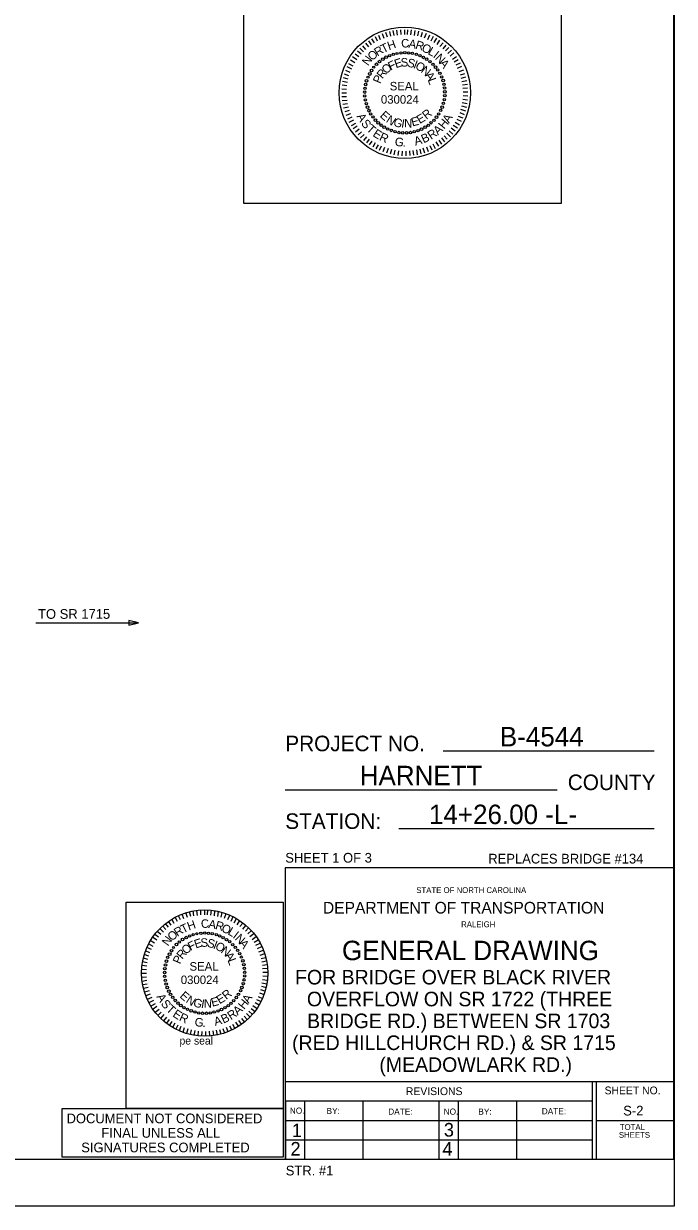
# Model space of a CAD drawing. Extents: x -20 to 509, y -659 to 21.
# Drawn here: x 197.5 to 264.5, y -176.3 to -54.6 of the extents above; entities that cross this region are included whole.
import ezdxf

# ---------------------------------------------------------------- set-up
doc = ezdxf.new("R2010")
doc.units = 0
for name, color, linetype in [('Arrowhead Terminators CELL', 7, 'Continuous'), ('Dimension Lines', 7, 'Continuous'), ('Peseal', 7, 'Continuous'), ('Plan Sheet CELL', 7, 'Continuous'), ('Plot Shape CELL', 7, 'Continuous'), ('Sheet Sticker Exception Certification CELL', 7, 'Continuous'), ('Subtitle Text', 7, 'Continuous'), ('Text', 7, 'Continuous'), ('Title Text', 7, 'Continuous'), ('User Information Notes', 7, 'Continuous'), ('User Information Notes CELL', 7, 'Continuous')]:
    doc.layers.add(name, color=color, linetype=linetype)

msp = doc.modelspace()

# ---------------------------------------------------------------- linework, layer by layer
at = {"layer": 'Arrowhead Terminators CELL'}
msp.add_lwpolyline([(209.32, -116.24), (208.32, -115.99), (208.32, -116.49)], close=True, dxfattribs=at)
at = {"layer": 'Dimension Lines'}
msp.add_line((198.75, -116.24), (209.32, -116.24), dxfattribs=at)
at = {"layer": 'Peseal'}
for p, q in [((233.94, -56.35), (233.72, -55.92)), ((234.25, -56.2), (234.06, -55.76)), ((234.62, -56.07), (234.44, -55.6)), ((234.97, -55.95), (234.81, -55.45)), ((235.31, -55.85), (235.19, -55.35)), ((235.66, -55.76), (235.56, -55.26)), ((236, -55.73), (235.94, -55.23)), ((236.37, -55.67), (236.34, -55.17)), ((236.75, -55.67), (236.75, -55.17)), ((237.03, -55.67), (237.06, -55.17)), ((237.37, -55.7), (237.44, -55.2)), ((237.75, -55.76), (237.81, -55.26)), ((238.09, -55.82), (238.19, -55.32)), ((238.44, -55.92), (238.56, -55.42)), ((238.78, -56.01), (238.97, -55.54)), ((239.12, -56.17), (239.34, -55.7)), ((239.47, -56.32), (239.69, -55.85)), ((232.5, -57.45), (232.12, -57.07)), ((232.75, -57.2), (232.44, -56.82)), ((233.03, -56.95), (232.72, -56.57)), ((233.31, -56.73), (233.03, -56.32)), ((233.62, -56.54), (233.37, -56.1)), ((239.78, -56.48), (240.03, -56.04)), ((240.09, -56.7), (240.37, -56.26)), ((240.37, -56.89), (240.69, -56.51)), ((240.69, -57.14), (241, -56.76)), ((240.94, -57.35), (241.28, -57.01)), ((231.59, -58.57), (231.16, -58.32)), ((231.81, -58.26), (231.37, -57.98)), ((232, -57.98), (231.62, -57.7)), ((232.25, -57.7), (231.87, -57.39)), ((241.19, -57.64), (241.56, -57.29)), ((241.41, -57.89), (241.81, -57.57)), ((241.66, -58.2), (242.06, -57.92)), ((241.84, -58.48), (242.25, -58.23)), ((231.12, -59.57), (230.66, -59.39)), ((231.28, -59.23), (230.81, -59.01)), ((231.44, -58.92), (230.97, -58.67)), ((242.03, -58.79), (242.47, -58.57)), ((242.19, -59.14), (242.62, -58.92)), ((242.34, -59.48), (242.81, -59.29)), ((230.84, -60.6), (230.34, -60.51)), ((230.91, -60.26), (230.44, -60.14)), ((231, -59.92), (230.53, -59.76)), ((242.47, -59.82), (242.94, -59.67)), ((242.56, -60.17), (243.03, -60.04)), ((242.62, -60.51), (243.12, -60.42)), ((242.69, -60.85), (243.19, -60.79)), ((230.75, -61.32), (230.25, -61.29)), ((230.75, -61.7), (230.25, -61.7)), ((230.75, -62.07), (230.25, -62.1)), ((230.78, -60.95), (230.31, -60.89)), ((242.72, -61.2), (243.22, -61.17)), ((242.75, -61.57), (243.25, -61.57)), ((242.75, -61.95), (243.25, -61.98)), ((230.81, -62.45), (230.31, -62.51)), ((230.84, -62.79), (230.37, -62.89)), ((230.94, -63.14), (230.44, -63.26)), ((242.59, -63.01), (243.09, -63.14)), ((242.66, -62.67), (243.16, -62.76)), ((242.72, -62.32), (243.22, -62.39)), ((231.03, -63.48), (230.56, -63.64)), ((231.16, -63.82), (230.69, -64.01)), ((231.31, -64.17), (230.84, -64.39)), ((231.47, -64.48), (231, -64.73)), ((242.09, -64.39), (242.56, -64.6)), ((242.25, -64.07), (242.72, -64.26)), ((242.41, -63.7), (242.87, -63.89)), ((242.5, -63.35), (243, -63.51)), ((231.66, -64.82), (231.22, -65.07)), ((231.84, -65.1), (231.44, -65.39)), ((232.06, -65.42), (231.66, -65.73)), ((232.28, -65.7), (231.94, -66.01)), ((241.31, -65.57), (241.69, -65.92)), ((241.53, -65.29), (241.94, -65.6)), ((241.72, -65.01), (242.16, -65.29)), ((241.94, -64.7), (242.37, -64.95)), ((232.56, -65.95), (232.19, -66.32)), ((232.81, -66.2), (232.5, -66.57)), ((233.09, -66.45), (232.81, -66.82)), ((233.37, -66.64), (233.09, -67.04)), ((233.69, -66.82), (233.44, -67.26)), ((239.62, -66.92), (239.87, -67.39)), ((239.94, -66.73), (240.22, -67.17)), ((240.25, -66.54), (240.53, -66.95)), ((240.53, -66.32), (240.84, -66.73)), ((240.81, -66.1), (241.12, -66.45)), ((241.06, -65.82), (241.44, -66.2)), ((234, -67.01), (233.78, -67.45)), ((234.31, -67.17), (234.12, -67.6)), ((234.66, -67.29), (234.5, -67.76)), ((235.03, -67.42), (234.87, -67.89)), ((235.37, -67.51), (235.25, -67.98)), ((235.72, -67.57), (235.62, -68.07)), ((236.09, -67.64), (236.03, -68.14)), ((236.47, -67.67), (236.44, -68.17)), ((236.84, -67.67), (236.84, -68.17)), ((237.22, -67.64), (237.25, -68.14)), ((237.59, -67.6), (237.66, -68.1)), ((237.94, -67.54), (238.03, -68.04)), ((238.28, -67.48), (238.41, -67.95)), ((238.62, -67.35), (238.78, -67.85)), ((238.97, -67.23), (239.16, -67.7)), ((239.31, -67.1), (239.53, -67.54)), ((214.36, -146.57), (214.2, -146.07)), ((214.7, -146.48), (214.58, -145.98)), ((215.04, -146.39), (214.95, -145.89)), ((215.39, -146.35), (215.33, -145.85)), ((215.76, -146.29), (215.73, -145.79)), ((216.14, -146.29), (216.14, -145.79)), ((216.42, -146.29), (216.45, -145.79)), ((216.76, -146.32), (216.83, -145.82)), ((217.14, -146.39), (217.2, -145.89)), ((217.48, -146.45), (217.58, -145.95)), ((217.83, -146.54), (217.95, -146.04)), ((212.42, -147.57), (212.11, -147.2)), ((212.7, -147.35), (212.42, -146.95)), ((213.01, -147.17), (212.76, -146.73)), ((213.33, -146.98), (213.11, -146.54)), ((213.64, -146.82), (213.45, -146.39)), ((214.01, -146.7), (213.83, -146.23)), ((218.17, -146.64), (218.36, -146.17)), ((218.51, -146.79), (218.73, -146.32)), ((218.86, -146.95), (219.08, -146.48)), ((219.17, -147.1), (219.42, -146.67)), ((219.48, -147.32), (219.76, -146.89)), ((219.76, -147.51), (220.08, -147.14)), ((211.39, -148.6), (211.01, -148.32)), ((211.64, -148.32), (211.26, -148.01)), ((211.89, -148.07), (211.51, -147.7)), ((212.14, -147.82), (211.83, -147.45)), ((220.08, -147.76), (220.39, -147.39)), ((220.33, -147.98), (220.67, -147.64)), ((220.58, -148.26), (220.95, -147.92)), ((220.79, -148.51), (221.2, -148.2)), ((210.67, -149.85), (210.2, -149.64)), ((210.83, -149.54), (210.36, -149.29)), ((210.98, -149.2), (210.54, -148.95)), ((211.2, -148.89), (210.76, -148.6)), ((221.04, -148.82), (221.45, -148.54)), ((221.23, -149.1), (221.64, -148.85)), ((221.42, -149.42), (221.86, -149.2)), ((221.58, -149.76), (222.01, -149.54)), ((210.29, -150.89), (209.83, -150.76)), ((210.39, -150.54), (209.92, -150.39)), ((210.51, -150.2), (210.04, -150.01)), ((221.73, -150.1), (222.2, -149.92)), ((221.86, -150.45), (222.33, -150.29)), ((221.95, -150.79), (222.42, -150.67)), ((210.14, -151.95), (209.64, -151.92)), ((210.17, -151.57), (209.7, -151.51)), ((210.23, -151.23), (209.73, -151.14)), ((222.01, -151.14), (222.51, -151.04)), ((222.08, -151.48), (222.58, -151.42)), ((222.11, -151.82), (222.61, -151.79)), ((210.14, -152.32), (209.64, -152.32)), ((210.14, -152.7), (209.64, -152.73)), ((210.2, -153.07), (209.7, -153.14)), ((222.04, -153.29), (222.54, -153.39)), ((222.11, -152.95), (222.61, -153.01)), ((222.14, -152.2), (222.64, -152.2)), ((222.14, -152.57), (222.64, -152.6)), ((210.23, -153.42), (209.76, -153.51)), ((210.33, -153.76), (209.83, -153.89)), ((210.42, -154.1), (209.95, -154.26)), ((210.54, -154.45), (210.08, -154.64)), ((221.79, -154.32), (222.26, -154.51)), ((221.89, -153.98), (222.39, -154.14)), ((221.98, -153.64), (222.48, -153.76)), ((210.7, -154.79), (210.23, -155.01)), ((210.86, -155.1), (210.39, -155.35)), ((211.04, -155.45), (210.61, -155.7)), ((211.23, -155.73), (210.83, -156.01)), ((221.11, -155.64), (221.54, -155.92)), ((221.33, -155.32), (221.76, -155.57)), ((221.48, -155.01), (221.95, -155.23)), ((221.64, -154.7), (222.11, -154.89)), ((211.45, -156.04), (211.04, -156.35)), ((211.67, -156.32), (211.33, -156.64)), ((211.95, -156.57), (211.58, -156.95)), ((212.2, -156.82), (211.89, -157.2)), ((219.92, -156.95), (220.23, -157.35)), ((220.2, -156.73), (220.51, -157.07)), ((220.45, -156.45), (220.83, -156.82)), ((220.7, -156.2), (221.08, -156.54)), ((220.92, -155.92), (221.33, -156.23)), ((212.48, -157.07), (212.2, -157.45)), ((212.76, -157.26), (212.48, -157.67)), ((213.08, -157.45), (212.83, -157.89)), ((213.39, -157.64), (213.17, -158.07)), ((213.7, -157.79), (213.51, -158.23)), ((214.04, -157.92), (213.89, -158.39)), ((214.42, -158.04), (214.26, -158.51)), ((214.76, -158.14), (214.64, -158.6)), ((215.11, -158.2), (215.01, -158.7)), ((215.48, -158.26), (215.42, -158.76)), ((216.61, -158.26), (216.64, -158.76)), ((216.98, -158.23), (217.04, -158.73)), ((217.33, -158.17), (217.42, -158.67)), ((217.67, -158.1), (217.79, -158.57)), ((218.01, -157.98), (218.17, -158.48)), ((218.36, -157.85), (218.54, -158.32)), ((218.7, -157.73), (218.92, -158.17)), ((219.01, -157.54), (219.26, -158.01)), ((219.33, -157.35), (219.61, -157.79)), ((219.64, -157.17), (219.92, -157.57)), ((215.86, -158.29), (215.83, -158.79)), ((216.23, -158.29), (216.23, -158.79))]:
    msp.add_line(p, q, dxfattribs=at)
for centre, radius in [((234.14, -58.46), 0.134), ((234.48, -58.21), 0.134), ((234.84, -58.01), 0.14), ((235.2, -57.84), 0.119), ((235.56, -57.71), 0.114), ((235.95, -57.62), 0.11), ((236.36, -57.57), 0.126), ((236.75, -57.54), 0.125), ((237.14, -57.57), 0.126), ((237.53, -57.6), 0.129), ((237.94, -57.71), 0.114), ((238.3, -57.84), 0.119), ((238.66, -58.03), 0.126), ((239, -58.21), 0.126), ((239.33, -58.45), 0.122), ((233.14, -59.73), 0.144), ((233.33, -59.37), 0.134), ((233.55, -59.03), 0.11), ((233.84, -58.73), 0.133), ((239.64, -58.73), 0.122), ((239.91, -59.03), 0.122), ((240.14, -59.32), 0.126), ((240.36, -59.67), 0.126), ((232.72, -60.82), 0.129), ((232.81, -60.43), 0.134), ((232.95, -60.06), 0.119), ((240.55, -60.03), 0.119), ((240.69, -60.4), 0.134), ((240.78, -60.79), 0.129), ((232.62, -61.6), 0.125), ((232.62, -61.99), 0.126), ((232.66, -61.21), 0.126), ((240.84, -61.18), 0.126), ((240.87, -61.57), 0.125), ((240.87, -61.96), 0.126), ((232.69, -62.4), 0.126), ((232.78, -62.79), 0.129), ((232.91, -63.15), 0.134), ((240.59, -63.15), 0.134), ((240.72, -62.76), 0.129), ((240.81, -62.37), 0.126), ((233.06, -63.51), 0.14), ((233.23, -63.85), 0.126), ((233.47, -64.15), 0.122), ((233.72, -64.48), 0.133), ((239.75, -64.49), 0.122), ((240.02, -64.18), 0.134), ((240.23, -63.85), 0.126), ((240.45, -63.48), 0.126), ((234, -64.76), 0.133), ((234.3, -64.99), 0.134), ((234.62, -65.21), 0.126), ((234.98, -65.4), 0.119), ((235.36, -65.54), 0.134), ((235.75, -65.67), 0.129), ((236.14, -65.76), 0.126), ((236.53, -65.79), 0.125), ((236.94, -65.79), 0.125), ((237.33, -65.76), 0.126), ((237.72, -65.67), 0.129), ((238.11, -65.56), 0.119), ((238.47, -65.42), 0.14), ((238.84, -65.21), 0.126), ((239.17, -65.01), 0.122), ((239.45, -64.76), 0.122), ((214.23, -148.64), 0.14), ((214.59, -148.46), 0.119), ((214.95, -148.34), 0.114), ((215.34, -148.24), 0.11), ((215.75, -148.2), 0.126), ((216.14, -148.17), 0.125), ((216.53, -148.2), 0.126), ((216.92, -148.23), 0.129), ((217.33, -148.34), 0.114), ((217.68, -148.46), 0.119), ((218.04, -148.65), 0.126), ((212.93, -149.65), 0.11), ((213.23, -149.35), 0.133), ((213.53, -149.09), 0.134), ((213.87, -148.84), 0.134), ((218.39, -148.84), 0.126), ((218.72, -149.07), 0.122), ((219.03, -149.35), 0.122), ((219.29, -149.65), 0.122), ((212.2, -151.06), 0.134), ((212.34, -150.68), 0.119), ((212.53, -150.35), 0.144), ((212.72, -149.99), 0.134), ((219.53, -149.95), 0.126), ((219.75, -150.29), 0.126), ((219.93, -150.65), 0.119), ((220.08, -151.03), 0.134), ((212.01, -152.23), 0.125), ((212.04, -151.84), 0.126), ((212.11, -151.45), 0.129), ((220.17, -151.42), 0.129), ((220.23, -151.81), 0.126), ((220.26, -152.2), 0.125), ((212.01, -152.62), 0.126), ((212.08, -153.03), 0.126), ((212.17, -153.42), 0.129), ((220.11, -153.39), 0.129), ((220.2, -152.99), 0.126), ((220.26, -152.59), 0.126), ((212.29, -153.78), 0.134), ((212.45, -154.14), 0.14), ((212.62, -154.48), 0.126), ((219.62, -154.48), 0.126), ((219.84, -154.1), 0.126), ((219.98, -153.78), 0.134), ((212.86, -154.78), 0.122), ((213.11, -155.1), 0.133), ((213.39, -155.39), 0.133), ((213.68, -155.62), 0.134), ((214.01, -155.84), 0.126), ((218.23, -155.84), 0.126), ((218.56, -155.64), 0.122), ((218.84, -155.39), 0.122), ((219.14, -155.12), 0.122), ((219.4, -154.81), 0.134), ((214.37, -156.03), 0.119), ((214.75, -156.17), 0.134), ((215.14, -156.29), 0.129), ((215.53, -156.39), 0.126), ((215.92, -156.42), 0.125), ((216.33, -156.42), 0.125), ((216.72, -156.39), 0.126), ((217.11, -156.29), 0.129), ((217.5, -156.18), 0.119), ((217.86, -156.04), 0.14)]:
    msp.add_circle(centre, radius, dxfattribs=at)
at = {"layer": 'Plan Sheet CELL'}
for p, q in [((264.43, -3.45), (264.43, -171.45)), ((262.44, -129.45), (240.7, -129.45)), ((252.44, -133.45), (224.44, -133.45)), ((262.44, -137.45), (236.12, -137.45)), ((264.43, -141.45), (224.44, -141.45)), ((224.44, -141.45), (224.44, -171.45)), ((224.44, -163.45), (264.43, -163.45)), ((256.04, -163.45), (256.04, -171.45)), ((256.44, -163.45), (256.44, -171.45)), ((224.44, -165.45), (256.05, -165.45)), ((224.46, -165.45), (224.46, -171.45)), ((226.43, -165.45), (226.43, -171.45)), ((232.43, -165.48), (232.43, -171.48)), ((240.24, -165.45), (240.24, -171.5)), ((242.24, -165.45), (242.24, -171.46)), ((248.24, -165.45), (248.24, -171.46)), ((224.44, -167.45), (256.12, -167.45)), ((256.44, -167.45), (264.36, -167.45)), ((224.44, -169.45), (256.05, -169.45)), ((8.43, -171.45), (264.43, -171.45)), ((264.5, -176.3), (264.5, -176.3))]:
    msp.add_line(p, q, dxfattribs=at)
msp.add_lwpolyline([(220.15, -73.02), (252.88, -73.02), (252.88, -51.02), (220.15, -51.02)], close=True, dxfattribs=at)
at = {"layer": 'Plot Shape CELL'}
msp.add_lwpolyline([(0, -0.3), (264.5, -0.3), (264.5, -176.3), (0, -176.3)], close=True, dxfattribs=at)
at = {"layer": 'Sheet Sticker Exception Certification CELL'}
msp.add_lwpolyline([(201.45, -166.24), (224.24, -166.24), (224.24, -171.25), (201.45, -171.25)], close=True, dxfattribs=at)
at = {"layer": 'User Information Notes'}
for p, q in [((236.75, -61.67), (236.75, -61.67)), ((252.88, -73.02), (252.88, -73.02)), ((216.14, -152.29), (216.14, -152.29))]:
    msp.add_line(p, q, dxfattribs=at)
msp.add_circle((236.75, -61.67), 6.77, dxfattribs=at)
at = {"layer": 'User Information Notes CELL'}
msp.add_line((216.14, -152.29), (216.14, -152.29), dxfattribs=at)
msp.add_lwpolyline([(208.04, -144.99), (224.24, -144.99), (224.24, -166.24), (208.04, -166.24)], close=True, dxfattribs=at)
msp.add_circle((216.14, -152.29), 6.5, dxfattribs=at)

# ---------------------------------------------------------------- texts
at = {"layer": 'Dimension Lines'}
msp.add_text('STR. #1', height=1, dxfattribs=at).set_placement((224.49, -173.12))
at = {"layer": 'Peseal'}
for s, height, rotation, p in [('R', 0.875, 32.9699, (233.94, -57.95)), ('T', 0.875, 25.943, (234.53, -57.6)), ('H', 0.875, 18.9162, (235.12, -57.29)), ('C', 0.875, 4.8625, (236.41, -57.04)), ('A', 0.875, 350.8088, (237.09, -57.01)), ('R', 0.875, 343.7819, (237.78, -57.1)), ('O', 0.875, 336.7551, (238.41, -57.35)), ('L', 0.875, 329.7282, (239.06, -57.64)), ('N', 0.875, 54.0504, (232.97, -58.95)), ('O', 0.875, 39.9967, (233.37, -58.42)), ('F', 0.875, 26.4777, (235.28, -59.39)), ('E', 0.875, 18.4448, (235.84, -59.14)), ('S', 0.875, 2.3789, (236.34, -58.98)), ('S', 0.875, 346.313, (236.94, -58.95)), ('I', 0.875, 338.28, (237.56, -59.1)), ('I', 0.875, 322.7014, (239.59, -57.98)), ('N', 0.875, 315.6745, (239.81, -58.17)), ('A', 0.875, 308.6477, (240.25, -58.64)), ('R', 0.875, 50.5765, (234.44, -60.29)), ('O', 0.875, 42.5436, (234.84, -59.79)), ('O', 0.875, 330.2471, (237.75, -59.14)), ('N', 0.875, 322.2141, (238.34, -59.51)), ('A', 0.875, 306.1483, (238.78, -59.89)), ('P', 0.875, 66.6424, (234.22, -60.79)), ('L', 0.875, 290.0824, (239.09, -60.32)), ('A', 0.887, 300.3993, (231.75, -64.09)), ('S', 0.887, 309.4349, (232.19, -64.85)), ('E', 0.875, 318.5179, (234.12, -64.1)), ('N', 0.875, 326.5361, (234.75, -64.64)), ('G', 0.875, 342.5725, (235.5, -65.04)), ('I', 0.875, 350.5906, (236.34, -65.23)), ('N', 0.875, 358.6088, (236.66, -65.23)), ('E', 0.875, 14.6452, (237.53, -65.14)), ('E', 0.875, 30.6815, (238.28, -64.89)), ('R', 0.875, 38.6997, (238.97, -64.45)), ('H', 0.887, 51.3597, (240.8, -65.47)), ('A', 0.887, 59.6007, (241.31, -64.85)), ('T', 0.887, 318.1096, (232.73, -65.5)), ('E', 0.887, 327.1453, (233.38, -66.08)), ('R', 0.887, 33.5776, (239.45, -66.52)), ('A', 0.887, 42.3241, (240.16, -66.06)), ('R', 0.888, 335.458, (234.05, -66.52)), ('G', 0.887, 353.3858, (235.68, -67.12)), ('A', 0.887, 15.7955, (237.84, -67.11)), ('B', 0.887, 24.8312, (238.68, -66.88)), ('.', 0.887, 2.1323, (236.52, -67.22)), ('T', 0.875, 25.943, (213.92, -148.23)), ('H', 0.875, 18.9162, (214.51, -147.92)), ('C', 0.875, 4.8625, (215.79, -147.67)), ('A', 0.875, 350.8088, (216.48, -147.64)), ('R', 0.875, 343.7819, (217.17, -147.73)), ('O', 0.875, 336.7551, (217.79, -147.98)), ('N', 0.875, 54.0504, (212.36, -149.57)), ('O', 0.875, 39.9967, (212.76, -149.04)), ('R', 0.875, 32.9699, (213.33, -148.57)), ('L', 0.875, 329.7282, (218.45, -148.26)), ('I', 0.875, 322.7014, (218.98, -148.6)), ('N', 0.875, 315.6745, (219.2, -148.79)), ('O', 0.875, 42.5436, (214.23, -150.42)), ('F', 0.875, 26.4777, (214.67, -150.01)), ('E', 0.875, 18.4448, (215.23, -149.76)), ('S', 0.875, 2.3789, (215.73, -149.6)), ('S', 0.875, 346.313, (216.33, -149.57)), ('I', 0.875, 338.28, (216.95, -149.73)), ('O', 0.875, 330.2471, (217.14, -149.76)), ('N', 0.875, 322.2141, (217.73, -150.14)), ('A', 0.875, 308.6477, (219.64, -149.26)), ('P', 0.875, 66.6424, (213.61, -151.42)), ('R', 0.875, 50.5765, (213.83, -150.92)), ('A', 0.875, 306.1483, (218.17, -150.51)), ('L', 0.875, 290.0824, (218.48, -150.95)), ('A', 0.887, 300.3993, (211.14, -154.72)), ('E', 0.875, 318.5179, (213.51, -154.73)), ('N', 0.875, 326.5361, (214.14, -155.26)), ('E', 0.875, 30.6815, (217.67, -155.51)), ('R', 0.875, 38.6997, (218.36, -155.07)), ('A', 0.887, 59.6007, (220.69, -155.47)), ('S', 0.887, 309.4349, (211.58, -155.47)), ('T', 0.887, 318.1096, (212.11, -156.12)), ('G', 0.875, 342.5725, (214.89, -155.67)), ('I', 0.875, 350.5906, (215.73, -155.85)), ('N', 0.875, 358.6088, (216.04, -155.85)), ('E', 0.875, 14.6452, (216.92, -155.76)), ('A', 0.887, 42.3241, (219.54, -156.68)), ('H', 0.887, 51.3597, (220.19, -156.09)), ('E', 0.887, 327.1453, (212.77, -156.71)), ('R', 0.888, 335.458, (213.44, -157.15)), ('G', 0.887, 353.3858, (215.07, -157.74)), ('A', 0.887, 15.7955, (217.23, -157.74)), ('B', 0.887, 24.8312, (218.07, -157.5)), ('R', 0.887, 33.5776, (218.84, -157.15)), ('.', 0.887, 2.1323, (215.91, -157.84))]:
    msp.add_text(s, height=height, rotation=rotation, dxfattribs=at).set_placement(p)
for s, p in [('SEAL', (235.19, -61.42)), ('030024', (234.29, -62.79)), ('SEAL', (214.58, -152.04)), ('030024', (213.68, -153.42))]:
    msp.add_text(s, height=0.875, dxfattribs=at).set_placement(p)
at = {"layer": 'Plan Sheet CELL'}
for s, height, p in [('PROJECT NO.', 1.6, (224.44, -129.45)), ('COUNTY', 1.6, (253.53, -133.45)), ('STATION:', 1.6, (224.44, -137.45)), ('SHEET 1 OF 3', 1, (224.44, -140.92)), ('STATE OF NORTH CAROLINA', 0.6, (237.93, -144.05)), ('DEPARTMENT OF TRANSPORTATION', 1.2, (228.32, -146.16)), ('RALEIGH', 0.6, (242.55, -147.57)), ('REVISIONS', 0.8, (236.86, -164.85)), ('SHEET NO.', 0.8, (257.32, -164.77)), ('NO.', 0.637, (224.91, -166.77)), ('BY:', 0.637, (228.69, -166.8)), ('DATE:', 0.637, (235.04, -166.87)), ('NO.', 0.637, (240.75, -166.87)), ('BY:', 0.637, (244.32, -166.87)), ('DATE:', 0.637, (250.85, -166.83)), ('1', 1.4, (225.12, -169.18)), ('3', 1.4, (240.77, -169.12)), ('TOTAL', 0.6, (258.89, -168.44)), ('SHEETS', 0.6, (258.79, -169.25)), ('2', 1.4, (224.98, -171.08)), ('4', 1.4, (240.62, -171.08))]:
    msp.add_text(s, height=height, dxfattribs=at).set_placement(p)
at = {"layer": 'Sheet Sticker Exception Certification CELL'}
for s, p in [('DOCUMENT NOT CONSIDERED', (201.92, -167.75)), ('FINAL UNLESS ALL', (205.5, -169.24)), ('SIGNATURES COMPLETED', (203.43, -170.74))]:
    msp.add_text(s, height=0.9978, dxfattribs=at).set_placement(p)
at = {"layer": 'Subtitle Text'}
for s, p in [('FOR BRIDGE OVER BLACK RIVER', (225.45, -153.46)), ('OVERFLOW ON SR 1722 (THREE', (226.67, -155.71)), ('BRIDGE RD.) BETWEEN SR 1703', (226.69, -157.96)), ('(RED HILLCHURCH RD.) & SR 1715', (225.14, -160.21)), ('(MEADOWLARK RD.)', (234.13, -162.46))]:
    msp.add_text(s, height=1.5, dxfattribs=at).set_placement(p)
at = {"layer": 'Text'}
for s, p in [('TO SR 1715', (198.98, -115.82)), ('REPLACES BRIDGE #134', (245.34, -141.01)), ('S-2', (259.24, -166.95))]:
    msp.add_text(s, height=1, dxfattribs=at).set_placement(p)
at = {"layer": 'Title Text'}
for s, p in [('B-4544', (246.54, -128.95)), ('HARNETT', (232.11, -132.95)), ('14+26.00 -L-', (239.24, -136.95)), ('GENERAL DRAWING', (230.28, -150.96))]:
    msp.add_text(s, height=2, dxfattribs=at).set_placement(p)
at = {"layer": 'User Information Notes CELL'}
msp.add_text('pe seal', height=0.8, dxfattribs=at).set_placement((213.55, -159.65))

doc.saveas('drawing.dxf')
